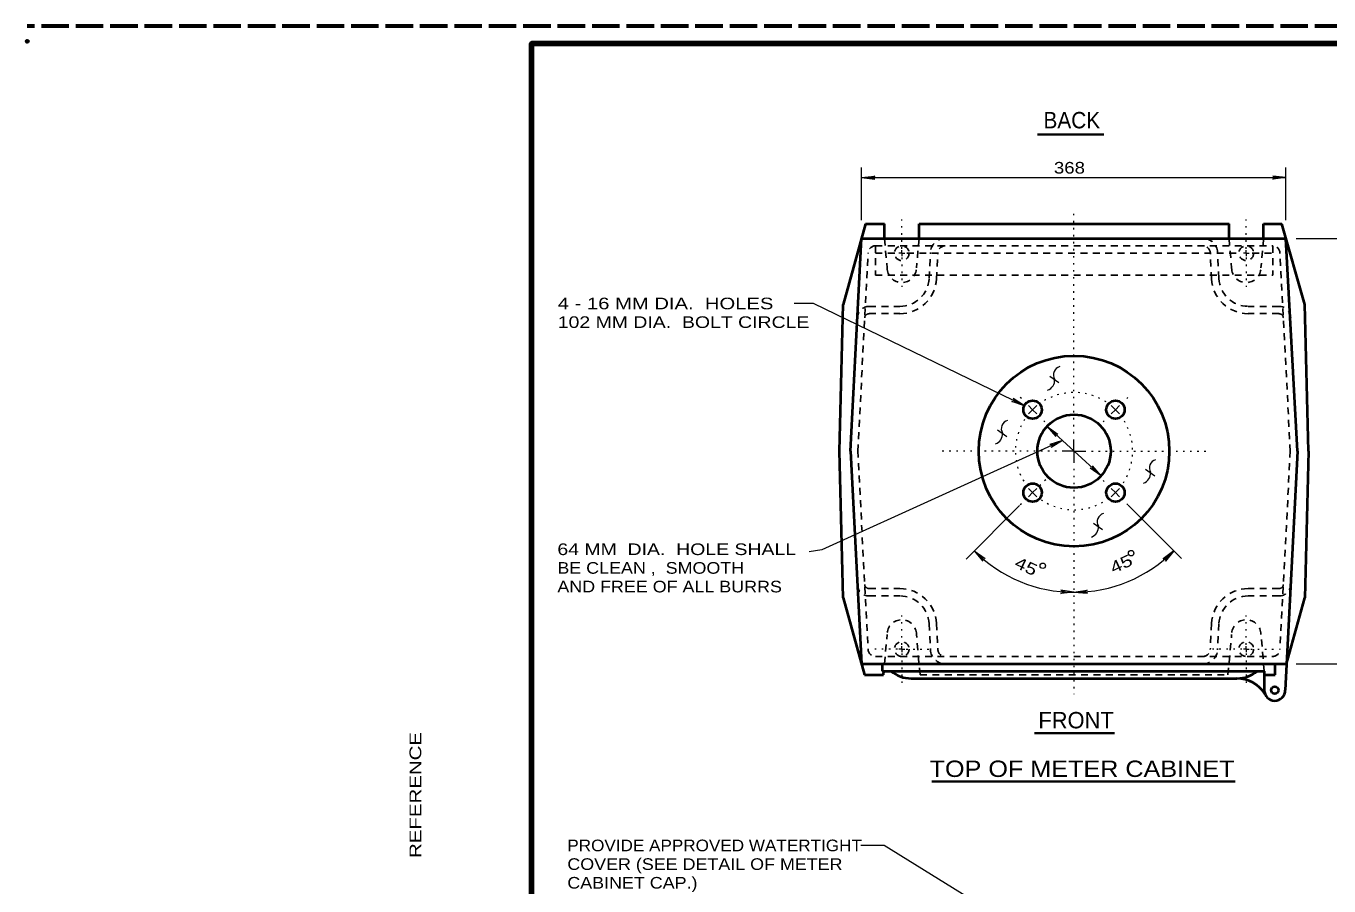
# Model space of a CAD drawing. Extents: x 312583 to 312853, y 144419 to 144586.
# Drawn here: x 312583.5 to 312668.6, y 144530 to 144586.2 of the extents above; entities that cross this region are included whole.
import ezdxf
from ezdxf.enums import TextEntityAlignment as Align

# ---------------------------------------------------------------- set-up
doc = ezdxf.new("R2010")
doc.units = 0
doc.header["$LTSCALE"] = 0.3
doc.header["$PDMODE"] = 32
doc.header["$PDSIZE"] = 0.15
for name, pattern in [('DOTTED', [1.5, 0.3, -1.2]), ('LONG_DASHED', [7.5, 6, -1.5]), ('SHORT_DASHED', [2.7, 1.5, -1.2])]:
    doc.linetypes.add(name, pattern=pattern)
for name, color, linetype, lineweight in [('1', 7, 'Continuous', 40), ('2', 7, 'Continuous', 13), ('63', 7, 'LONG_DASHED', 60)]:
    doc.layers.add(name, color=color, linetype=linetype, lineweight=lineweight)

msp = doc.modelspace()

# ---------------------------------------------------------------- linework, layer by layer
at = {"layer": '1'}
for p, q in [((312638.3314, 144573.2963), (312636.8671, 144568.0293)), ((312638.3314, 144573.2963), (312639.5658, 144573.2963)), ((312639.5658, 144572.3379), (312639.5658, 144573.2963)), ((312641.8274, 144573.2963), (312662.0904, 144573.2963)), ((312641.8274, 144572.3379), (312641.8274, 144573.2963)), ((312662.0904, 144572.3379), (312662.0904, 144573.2963)), ((312664.3521, 144573.2963), (312665.5328, 144573.2963)), ((312664.3521, 144572.3379), (312664.3521, 144573.2963)), ((312667.0508, 144568.0293), (312665.5328, 144573.2963)), ((312637.3424, 144558.4459), (312638.0631, 144572.3379)), ((312638.0631, 144572.3379), (312665.8088, 144572.3379)), ((312666.5754, 144558.4459), (312665.8088, 144572.3379)), ((312667.2884, 144558.4459), (312667.0508, 144568.0293)), ((312637.3424, 144558.4459), (312638.0631, 144544.5463)), ((312666.5754, 144558.4459), (312665.7628, 144542.8213)), ((312667.2884, 144558.4459), (312667.0508, 144548.8626)), ((312636.8671, 144548.8626), (312638.2624, 144543.8333)), ((312665.8548, 144544.5463), (312667.0508, 144548.8626)), ((312638.0631, 144544.5463), (312665.8548, 144544.5463)), ((312639.4124, 144544.5233), (312639.4124, 144544.0709)), ((312665.0958, 144543.8333), (312665.0958, 144544.5463)), ((312638.2624, 144543.8333), (312639.5044, 144543.8333)), ((312639.4124, 144544.0709), (312664.3904, 144544.0709)), ((312639.5044, 144543.8333), (312639.5198, 144544.0709)), ((312641.3138, 144543.5879), (312662.6041, 144543.5879)), ((312664.3904, 144544.0709), (312664.3904, 144542.8213)), ((312664.3981, 144543.8333), (312665.0958, 144543.8333))]:
    msp.add_line(p, q, dxfattribs=at)
at = {"layer": '1', "linetype": 'SHORT_DASHED', "lineweight": 25}
for p, q in [((312639.5658, 144572.3379), (312639.7421, 144570.4213)), ((312641.8274, 144572.3379), (312641.6588, 144570.4213)), ((312662.0904, 144572.3379), (312662.2591, 144570.4213)), ((312664.3521, 144572.3379), (312664.1758, 144570.4213)), ((312637.8254, 144558.4229), (312638.4924, 144571.4103)), ((312638.9754, 144571.8626), (312664.9424, 144571.8626)), ((312638.9754, 144571.8626), (312638.9754, 144569.9459)), ((312642.4868, 144569.7313), (312642.5711, 144571.4333)), ((312642.9698, 144569.7006), (312643.0541, 144571.4026)), ((312660.9481, 144569.7006), (312660.8638, 144571.4026)), ((312661.4311, 144569.7313), (312661.3391, 144571.4333)), ((312664.9424, 144571.8626), (312664.9424, 144569.9459)), ((312666.0924, 144558.4229), (312665.4178, 144571.4103)), ((312638.9754, 144571.3796), (312640.3094, 144571.3796)), ((312641.0378, 144571.3796), (312662.8188, 144571.3796)), ((312663.6008, 144571.3796), (312664.9424, 144571.3796)), ((312638.9754, 144569.9459), (312664.9424, 144569.9459)), ((312638.5614, 144567.9066), (312640.5778, 144567.9066)), ((312638.5614, 144567.4313), (312640.5778, 144567.4313)), ((312665.3564, 144567.9066), (312663.3401, 144567.9066)), ((312665.3564, 144567.4313), (312663.3401, 144567.4313)), ((312637.8254, 144558.4689), (312638.4924, 144545.4816)), ((312666.0924, 144558.4689), (312665.4178, 144545.4816)), ((312638.5614, 144549.4606), (312640.5778, 144549.4606)), ((312665.3564, 144549.4606), (312663.3401, 144549.4606)), ((312638.5614, 144548.9853), (312640.5778, 144548.9853)), ((312665.3564, 144548.9853), (312663.3401, 144548.9853)), ((312642.4868, 144547.1606), (312642.5711, 144545.4586)), ((312642.9698, 144547.1836), (312643.0541, 144545.4816)), ((312660.9481, 144547.1836), (312660.8638, 144545.4816)), ((312661.4311, 144547.1606), (312661.3391, 144545.4586)), ((312639.5658, 144544.5463), (312639.7421, 144546.4629)), ((312641.8888, 144543.8333), (312641.6588, 144546.4629)), ((312662.0214, 144543.8333), (312662.2591, 144546.4629)), ((312664.3904, 144544.0709), (312664.1758, 144546.4629)), ((312638.9754, 144545.0293), (312664.9424, 144545.0293)), ((312641.8888, 144543.8333), (312662.0214, 144543.8333))]:
    msp.add_line(p, q, dxfattribs=at)
at = {"layer": '1', "lineweight": 158}
msp.add_lwpolyline([(312616.5, 144423.1446), (312616.5, 144585.0846), (312849, 144585.0846)], dxfattribs=at)
at = {"layer": '1'}
msp.add_lwpolyline([(312636.8671, 144548.8626), (312636.6218, 144558.4459), (312636.8671, 144568.0293)], dxfattribs=at)
at = {"layer": '1', "linetype": 'SHORT_DASHED', "lineweight": 25}
for centre in [(312640.6966, 144571.3815), (312663.2174, 144571.3815), (312640.6966, 144545.5065), (312663.2174, 144545.5065)]:
    msp.add_circle(centre, 0.4792, dxfattribs=at)
at = {"layer": '1'}
for centre, radius in [((312651.957, 144558.444), 6.2292), ((312649.2468, 144561.1542), 0.599), ((312654.6672, 144561.1542), 0.599), ((312651.957, 144558.444), 2.3958), ((312649.2468, 144555.7339), 0.599), ((312654.6672, 144555.7339), 0.599), ((312665.0766, 144542.8194), 0.2396)]:
    msp.add_circle(centre, radius, dxfattribs=at)
at = {"layer": '1', "linetype": 'SHORT_DASHED', "lineweight": 25}
for centre, radius, start, end in [((312643.5298, 144571.3815), 0.9583, 90, 177.11172), ((312660.3843, 144571.3815), 0.9583, 2.88828, 90), ((312638.9724, 144571.3815), 0.4792, 90, 177.03696), ((312643.5298, 144571.3815), 0.4792, 90, 177.11172), ((312660.3843, 144571.3815), 0.4792, 2.88828, 90), ((312664.9417, 144571.3815), 0.4792, 2.96304, 90), ((312640.6966, 144570.4232), 0.9583, 180, 0), ((312640.5732, 144569.8233), 1.9167, 270, 357.13759), ((312640.5732, 144569.8233), 2.3958, 270, 357.13759), ((312663.3409, 144569.8233), 2.3958, 182.86241, 270), ((312663.3409, 144569.8233), 1.9167, 182.86241, 270), ((312663.2174, 144570.4232), 0.9583, 180, 0), ((312638.5599, 144567.1399), 0.7667, 90, 177.03906), ((312638.5599, 144567.1399), 0.2875, 90, 177.03906), ((312665.3541, 144567.1399), 0.7667, 2.96094, 90), ((312665.3541, 144567.1399), 0.2875, 2.96094, 90), ((312638.5599, 144549.7481), 0.7667, 182.96094, 270), ((312638.5599, 144549.7481), 0.2875, 182.96094, 270), ((312640.5732, 144547.0648), 2.3958, 2.86241, 90), ((312663.3409, 144547.0648), 2.3958, 90, 177.13759), ((312665.3541, 144549.7481), 0.2875, 270, 357.03906), ((312665.3541, 144549.7481), 0.7667, 270, 357.03906), ((312640.5732, 144547.0648), 1.9167, 2.86241, 90), ((312663.3409, 144547.0648), 1.9167, 90, 177.13759), ((312640.6966, 144546.4648), 0.9583, 0, 180), ((312663.2174, 144546.4648), 0.9583, 0, 180), ((312638.9724, 144545.5065), 0.4792, 182.96304, 270), ((312643.5298, 144545.5065), 0.9583, 182.88828, 270), ((312643.5298, 144545.5065), 0.4792, 182.88828, 270), ((312660.3843, 144545.5065), 0.4792, 270, 357.11172), ((312660.3843, 144545.5065), 0.9583, 270, 357.11172), ((312664.9417, 144545.5065), 0.4792, 270, 357.03696)]:
    msp.add_arc(centre, radius, start, end, dxfattribs=at)
at = {"layer": '1', "linetype": 'DOTTED', "lineweight": 13}
for start, end in [(56.92932, 123.4994), (147.52661, 213.80923), (327.28505, 33.3722), (236.00023, 301.94161)]:
    msp.add_arc((312651.957, 144558.444), 3.8333, start, end, dxfattribs=at)
at = {"layer": '1'}
for centre, radius, start, end in [((312641.3129, 144545.6971), 2.1073, 230.75329, 269.91814), ((312662.6011, 144545.6971), 2.1073, 270.08186, 309.24671), ((312662.5968, 144541.4167), 2.1732, 32.22812, 89.80783), ((312665.0766, 144542.8194), 0.6862, 180, 0)]:
    msp.add_arc(centre, radius, start, end, dxfattribs=at)
msp.add_point((312583.526, 144585.2246), dxfattribs=at)
at = {"layer": '2', "lineweight": 35}
for p, q in [((312649.5766, 144579.1295), (312653.9006, 144579.1295)), ((312649.3791, 144540.0048), (312654.6078, 144540.0048)), ((312642.6521, 144536.8566), (312662.4952, 144536.8566))]:
    msp.add_line(p, q, dxfattribs=at)
at = {"layer": '2'}
for p, q in [((312638.0631, 144573.5416), (312638.0631, 144576.9839)), ((312665.8088, 144573.5416), (312665.8088, 144576.9839)), ((312638.0631, 144576.3169), (312638.9294, 144576.4243)), ((312638.0631, 144576.3169), (312665.8088, 144576.3169)), ((312638.0631, 144576.3169), (312638.9294, 144576.2096)), ((312638.9294, 144576.4243), (312638.6534, 144576.3169)), ((312638.9294, 144576.2096), (312638.6534, 144576.3169)), ((312664.9424, 144576.4243), (312665.2184, 144576.3169)), ((312665.8088, 144576.3169), (312664.9424, 144576.4243)), ((312664.9424, 144576.2096), (312665.2184, 144576.3169)), ((312665.8088, 144576.3169), (312664.9424, 144576.2096)), ((312666.4834, 144572.3379), (312672.7471, 144572.3379)), ((312640.7004, 144571.3796), (312640.7004, 144571.5713)), ((312663.2174, 144571.3796), (312663.2174, 144571.5713)), ((312640.7004, 144571.3796), (312640.5088, 144571.3796)), ((312640.7004, 144571.3796), (312640.8921, 144571.3796)), ((312640.7004, 144571.3796), (312640.7004, 144571.1879)), ((312663.2174, 144571.3796), (312663.0258, 144571.3796)), ((312663.2174, 144571.3796), (312663.4091, 144571.3796)), ((312663.2174, 144571.3796), (312663.2174, 144571.1879)), ((312634.9351, 144568.0829), (312633.6548, 144568.0829)), ((312648.7121, 144561.4129), (312634.9351, 144568.0829)), ((312650.3681, 144563.3449), (312650.9738, 144562.9233)), ((312647.8841, 144561.6966), (312648.1754, 144561.6736)), ((312648.7121, 144561.4129), (312647.8841, 144561.6966)), ((312647.9761, 144561.8883), (312648.1754, 144561.6736)), ((312648.7121, 144561.4129), (312647.9761, 144561.8883)), ((312649.2488, 144561.1523), (312648.9728, 144561.4283)), ((312649.2488, 144561.1523), (312649.5171, 144561.4283)), ((312654.6691, 144561.1523), (312654.3931, 144561.4283)), ((312654.6691, 144561.1523), (312654.9374, 144561.4283)), ((312649.2488, 144561.1523), (312648.9728, 144560.8839)), ((312649.2488, 144561.1523), (312649.5171, 144560.8839)), ((312654.6691, 144561.1523), (312654.3931, 144560.8839)), ((312654.6691, 144561.1523), (312654.9374, 144560.8839)), ((312646.9564, 144559.8259), (312647.5621, 144559.4043)), ((312650.1918, 144560.0636), (312653.7261, 144556.8206)), ((312650.1918, 144560.0636), (312650.7591, 144559.4043)), ((312650.1918, 144560.0636), (312650.9048, 144559.5576)), ((312650.7591, 144559.4043), (312650.6288, 144559.6649)), ((312650.9048, 144559.5576), (312650.6288, 144559.6649)), ((312651.2038, 144559.1359), (312635.4718, 144551.9906)), ((312651.2038, 144559.1359), (312650.3681, 144558.8753)), ((312650.3681, 144558.8753), (312650.6671, 144558.8983)), ((312651.2038, 144559.1359), (312650.4601, 144558.6836)), ((312650.4601, 144558.6836), (312650.6671, 144558.8983)), ((312651.9551, 144558.4459), (312651.9551, 144559.2126)), ((312651.9551, 144558.4459), (312651.1884, 144558.4459)), ((312651.9551, 144558.4459), (312652.7218, 144558.4459)), ((312651.9551, 144558.4459), (312651.9551, 144557.6793)), ((312653.0131, 144557.3343), (312653.2891, 144557.2193)), ((312653.7261, 144556.8206), (312653.0131, 144557.3343)), ((312653.1588, 144557.4876), (312653.2891, 144557.2193)), ((312653.7261, 144556.8206), (312653.1588, 144557.4876)), ((312656.6318, 144557.2653), (312657.2374, 144556.8359)), ((312649.2488, 144555.7319), (312648.9728, 144556.0079)), ((312649.2488, 144555.7319), (312648.9728, 144555.4636)), ((312649.2488, 144555.7319), (312649.5171, 144556.0079)), ((312649.2488, 144555.7319), (312649.5171, 144555.4636)), ((312654.6691, 144555.7319), (312654.3931, 144556.0079)), ((312654.6691, 144555.7319), (312654.3931, 144555.4636)), ((312654.6691, 144555.7319), (312654.9374, 144556.0079)), ((312654.6691, 144555.7319), (312654.9374, 144555.4636)), ((312648.3978, 144554.8809), (312644.9094, 144551.3926)), ((312655.4894, 144554.9116), (312658.9854, 144551.4233)), ((312653.2201, 144553.7463), (312653.8258, 144553.3169)), ((312635.4718, 144551.9906), (312634.6462, 144551.8569)), ((312645.4384, 144551.9216), (312646.0058, 144551.2623)), ((312645.4384, 144551.9216), (312646.1514, 144551.4233)), ((312658.4794, 144551.9216), (312657.7818, 144551.4003)), ((312658.4794, 144551.9216), (312657.9274, 144551.2469)), ((312646.0058, 144551.2623), (312645.8754, 144551.5306)), ((312646.1514, 144551.4233), (312645.8754, 144551.5306)), ((312657.7818, 144551.4003), (312658.0578, 144551.5153)), ((312657.9274, 144551.2469), (312658.0578, 144551.5153)), ((312651.0964, 144549.3533), (312651.3648, 144549.2383)), ((312651.9551, 144549.2229), (312651.0964, 144549.3533)), ((312651.9551, 144549.2229), (312652.8138, 144549.3686)), ((312652.8138, 144549.3686), (312652.5454, 144549.2536)), ((312652.8291, 144549.1539), (312652.5454, 144549.2536)), ((312651.0888, 144549.1386), (312651.3648, 144549.2383)), ((312651.9551, 144549.2229), (312651.0888, 144549.1386)), ((312651.9551, 144549.2229), (312652.8291, 144549.1539)), ((312640.7004, 144545.5046), (312640.5088, 144545.5046)), ((312640.7004, 144545.5046), (312640.7004, 144545.6963)), ((312640.7004, 144545.5046), (312640.8921, 144545.5046)), ((312640.7004, 144545.5046), (312640.7004, 144545.3129)), ((312663.2174, 144545.5046), (312663.0258, 144545.5046)), ((312663.2174, 144545.5046), (312663.2174, 144545.6963)), ((312663.2174, 144545.5046), (312663.4091, 144545.5046)), ((312663.2174, 144545.5046), (312663.2174, 144545.3129)), ((312666.4834, 144544.5463), (312672.7471, 144544.5463))]:
    msp.add_line(p, q, dxfattribs=at)
at = {"layer": '2', "linetype": 'DOTTED'}
for p, q in [((312651.9551, 144559.5959), (312651.9551, 144574.1933)), ((312640.7004, 144571.6709), (312640.7004, 144573.5876)), ((312663.2174, 144571.6709), (312663.2174, 144573.5876)), ((312640.7004, 144571.0959), (312640.7004, 144569.1793)), ((312663.2174, 144571.0959), (312663.2174, 144569.1793)), ((312648.8424, 144561.5586), (312648.3748, 144562.0263)), ((312655.0754, 144561.5586), (312655.6351, 144562.1259)), ((312649.6551, 144560.7459), (312650.0691, 144560.3396)), ((312654.2628, 144560.7459), (312653.7798, 144560.2706)), ((312650.8051, 144558.4459), (312643.1384, 144558.4459)), ((312653.1051, 144558.4459), (312660.7718, 144558.4459)), ((312651.9551, 144557.2959), (312651.9551, 144542.5683)), ((312649.7088, 144556.1919), (312650.1458, 144556.6289)), ((312654.2628, 144556.1383), (312653.8334, 144556.5676)), ((312648.8424, 144555.3256), (312648.3978, 144554.8809)), ((312655.0754, 144555.3256), (312655.4894, 144554.9193)), ((312640.7004, 144545.7959), (312640.7004, 144547.7126)), ((312663.2174, 144545.7959), (312663.2174, 144547.7126)), ((312640.4091, 144545.5046), (312638.7224, 144545.5046)), ((312640.7004, 144545.2209), (312640.7004, 144543.3043)), ((312640.9841, 144545.5046), (312642.8164, 144545.5046)), ((312662.9338, 144545.5046), (312661.0171, 144545.5046)), ((312663.2174, 144545.2209), (312663.2174, 144543.3043)), ((312663.5088, 144545.5046), (312665.1648, 144545.5046))]:
    msp.add_line(p, q, dxfattribs=at)
at = {"layer": '2'}
msp.add_lwpolyline([(312648.6583, 144527.0203), (312639.5426, 144532.6783), (312638.0246, 144532.6783)], dxfattribs=at)
for centre in [(312655.6886, 144551.7758), (312649.9136, 144550.9517)]:
    msp.add_circle(centre, 0.1797, dxfattribs=at)
for centre, radius, start, end in [((312651.1666, 144563.4299), 0.5555, 104.98164, 210.86052), ((312650.0052, 144563.0824), 0.6875, 289.38376, 5.22592), ((312647.7569, 144559.9109), 0.5555, 104.98164, 210.86052), ((312646.5955, 144559.5634), 0.6875, 289.38376, 5.22592), ((312657.4341, 144557.3464), 0.5555, 104.98164, 210.86052), ((312656.2727, 144556.9989), 0.6875, 289.38376, 5.22592), ((312654.0244, 144553.8274), 0.5555, 104.98164, 210.86052), ((312652.863, 144553.4799), 0.6875, 289.38376, 5.22592), ((312651.957, 144558.444), 9.225, 225, 270), ((312651.957, 144558.444), 9.225, 270, 315.01684)]:
    msp.add_arc(centre, radius, start, end, dxfattribs=at)
at = {"layer": '63'}
msp.add_line((312851.75, 144586.2246), (312583.526, 144586.2246), dxfattribs=at)

# ---------------------------------------------------------------- texts
at = {"layer": '1', "width": 1.3}
msp.add_text('REFERENCE                                                              ', height=0.7682, rotation=90, dxfattribs=at).set_placement((312609.2854, 144531.8549))
at = {"layer": '2'}
for s, width, p in [('BACK', 0.95, (312651.8118, 144579.5405)), ('TOP OF METER CABINET', 1.15, (312652.4808, 144537.1505))]:
    msp.add_text(s, height=1.07, dxfattribs=dict(at, width=width)).set_placement(p, align=Align.CENTER)
for s, width, p in [('368 ', 1.2, (312650.6388, 144576.5843)), ('4 - 16 MM DIA.  HOLES', 1.3, (312618.2079, 144567.7139)), ('102 MM DIA.  BOLT CIRCLE', 1.25, (312618.2079, 144566.4939)), ('64 MM  DIA.  HOLE SHALL', 1.25, (312618.1833, 144551.6523)), ('BE CLEAN ,  SMOOTH', 1.15, (312618.1833, 144550.4323)), ('AND FREE OF ALL BURRS', 1.15, (312618.1833, 144549.2123)), ('PROVIDE APPROVED WATERTIGHT', 1.1, (312618.8347, 144532.2939)), ('COVER (SEE DETAIL OF METER', 1.15, (312618.8347, 144531.0739)), ('CABINET CAP.)', 1.15, (312618.8347, 144529.8539))]:
    msp.add_text(s, height=0.76, dxfattribs=dict(at, width=width)).set_placement(p)
at = {"layer": '2', "width": 1.3}
for rotation, p in [(335, (312648.0001, 144550.8878)), (25, (312654.5349, 144550.4202))]:
    msp.add_text('45', height=0.76, rotation=rotation, dxfattribs=at).set_placement(p)
at = {"layer": '2'}
msp.add_text('FRONT', height=1.07, dxfattribs=at).set_placement((312652.0888, 144540.3274), align=Align.CENTER)

doc.saveas('drawing.dxf')
